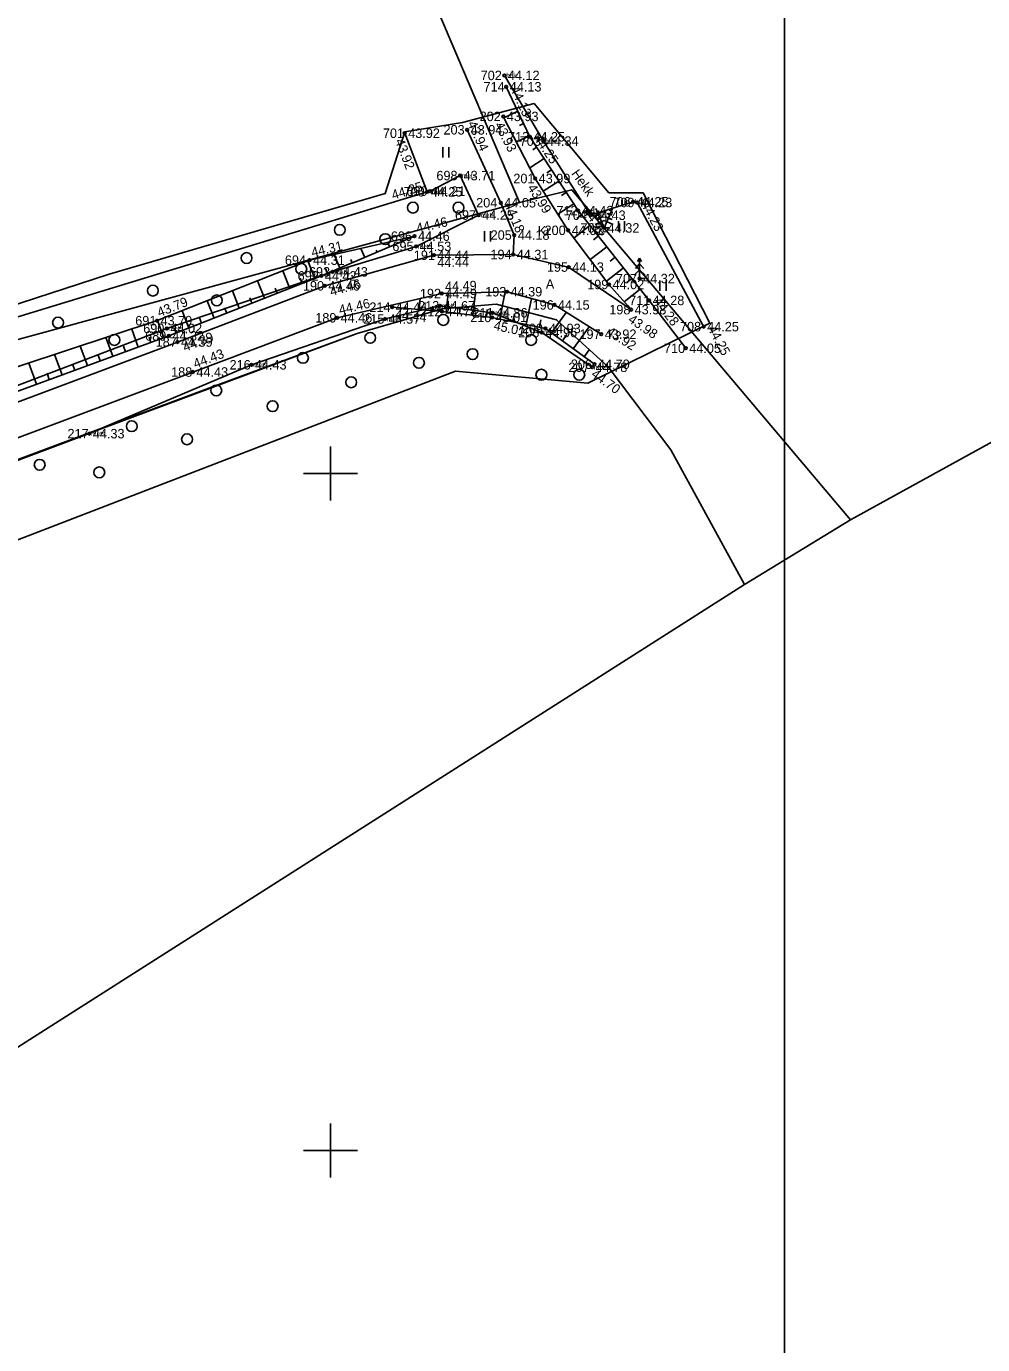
# Model space of a CAD drawing. Extents: x 505800 to 507326, y 6540058 to 6542128.
# Drawn here: x 506527.5 to 506598.2, y 6540335.7 to 6540433 of the extents above; entities that cross this region are included whole.
import ezdxf

# ---------------------------------------------------------------- set-up
doc = ezdxf.new("R2010")
doc.units = 0
for name, color, linetype in [('AED', 7, 'Continuous'), ('HALJASTUS', 7, 'Continuous'), ('KORGUS-EH2000', 7, 'Continuous'), ('MAAMUDEL', 7, 'Continuous'), ('MOOTKORG-EH2000', 7, 'Continuous'), ('MOOTMPUNKT', 7, 'Continuous'), ('MOOTNR', 7, 'Continuous'), ('MOOTPIIR', 7, 'Continuous'), ('PIIR', 7, 'Continuous'), ('PUU', 7, 'Continuous'), ('RELJEEF', 7, 'Continuous'), ('TEE', 7, 'Continuous'), ('VORK', 7, 'Continuous'), ('VORMISTUS', 7, 'Continuous')]:
    doc.layers.add(name, color=color, linetype=linetype)

msp = doc.modelspace()

# ---------------------------------------------------------------- linework, layer by layer
at = {"layer": 'AED'}
msp.add_line((506572.65, 6540420.013), (506577.572, 6540410.845), dxfattribs=at)
msp.add_lwpolyline([(506555.478, 6540425.13), (506557.144, 6540420.803), (506466.236, 6540393.054), (506460.432, 6540391.544), (506453.59, 6540403.335)], dxfattribs=at)
at = {"layer": 'HALJASTUS'}
for p, q in [((506558.288, 6540424.099), (506558.288, 6540423.338)), ((506558.743, 6540424.099), (506558.743, 6540423.338)), ((506561.37, 6540417.89), (506561.37, 6540417.129)), ((506561.825, 6540417.89), (506561.825, 6540417.129)), ((506571.271, 6540418.646), (506571.271, 6540417.884)), ((506571.726, 6540418.646), (506571.726, 6540417.884)), ((506574.337, 6540414.25), (506574.337, 6540413.489)), ((506574.792, 6540414.25), (506574.792, 6540413.489))]:
    msp.add_line(p, q, dxfattribs=at)
for points in [[(506572.366, 6540420.068), (506569.205, 6540419.074), (506565.725, 6540424.549), (506562.844, 6540429.401)], [(506557.354, 6540420.848), (506559.573, 6540422.003), (506560.946, 6540419.087), (506556.322, 6540416.775), (506550.153, 6540414.892), (506537.908, 6540410.713), (506520.721, 6540404.149), (506508.163, 6540400.843), (506496.611, 6540397.759), (506493.383, 6540398.082), (506483.471, 6540394.371), (506478, 6540394.292), (506477.343, 6540396.444)], [(506413.936, 6540356.957), (506411.035, 6540361.537), (506411.476, 6540364.066), (506416.66, 6540366.321), (506428.112, 6540371.138), (506442.602, 6540377.508), (506445.225, 6540379.984), (506450.028, 6540381.664), (506456.825, 6540384.191), (506464.626, 6540386.148), (506480.51, 6540389.107), (506500.858, 6540392.966), (506504.844, 6540391.729), (506512.52, 6540393.396), (506515.37, 6540396.647), (506532.173, 6540402.941), (506544.149, 6540408.028), (506554.027, 6540411.411), (506558.081, 6540412.384), (506561.957, 6540411.866), (506565.619, 6540410.412), (506569.33, 6540407.843)]]:
    msp.add_lwpolyline(points, dxfattribs=at)
for centre in [(506556.087, 6540419.636), (506559.45, 6540419.636), (506550.682, 6540417.993), (506554.045, 6540417.312), (506543.796, 6540415.91), (506547.84, 6540415.109), (506536.87, 6540413.506), (506541.594, 6540412.785), (506529.863, 6540411.143), (506558.334, 6540411.341), (506534.027, 6540409.861), (506552.929, 6540410.019), (506564.82, 6540409.859), (506560.496, 6540408.817), (506547.964, 6540408.537), (506556.532, 6540408.176), (506551.527, 6540406.734), (506565.58, 6540407.295), (506568.383, 6540407.295), (506541.558, 6540406.133), (506545.722, 6540404.971), (506535.312, 6540403.489), (506539.396, 6540402.528), (506528.506, 6540400.645), (506532.91, 6540400.084)]:
    msp.add_circle(centre, 0.4, dxfattribs=at)
at = {"layer": 'KORGUS-EH2000'}
for centre in [(506562.844, 6540429.401), (506562.984, 6540428.562), (506562.766, 6540426.375), (506555.478, 6540425.13), (506560.096, 6540425.387), (506564.728, 6540424.868), (506565.725, 6540424.549), (506559.573, 6540422.003), (506565.119, 6540421.785), (506557.144, 6540420.803), (506557.354, 6540420.848), (506562.58, 6540419.998), (506572.366, 6540420.068), (506572.65, 6540420.013), (506560.946, 6540419.087), (506568.304, 6540419.414), (506569.205, 6540419.074), (506563.58, 6540417.61), (506567.566, 6540417.958), (506570.222, 6540418.135), (506556.207, 6540417.529), (506556.322, 6540416.775), (506548.446, 6540415.756), (506557.625, 6540416.116), (506563.498, 6540416.176), (506550.153, 6540414.892), (506567.596, 6540415.247), (506549.32, 6540414.59), (506549.569, 6540413.859), (506570.577, 6540413.961), (506572.841, 6540414.395), (506558.214, 6540413.286), (506563.041, 6540413.426), (506573.539, 6540412.782), (506554.549, 6540412.283), (506558.081, 6540412.384), (506558.234, 6540411.96), (506561.957, 6540411.866), (506566.541, 6540412.447), (506572.209, 6540412.1), (506537.177, 6540411.287), (506550.483, 6540411.5), (506554.027, 6540411.411), (506561.931, 6540411.527), (506577.572, 6540410.845), (506537.908, 6540410.713), (506538.05, 6540410.165), (506565.619, 6540410.412), (506565.885, 6540410.713), (506570.003, 6540410.285), (506538.684, 6540409.711), (506576.247, 6540409.247), (506544.149, 6540408.028), (506569.506, 6540408.068), (506539.83, 6540407.495), (506569.33, 6540407.843), (506532.173, 6540402.941)]:
    msp.add_circle(centre, 0.1, dxfattribs=at)
at = {"layer": 'MOOTMPUNKT'}
for centre in [(506562.844, 6540429.401), (506562.984, 6540428.562), (506562.766, 6540426.375), (506555.478, 6540425.13), (506560.096, 6540425.387), (506564.728, 6540424.868), (506565.725, 6540424.549), (506559.573, 6540422.003), (506565.119, 6540421.785), (506557.144, 6540420.803), (506557.354, 6540420.848), (506562.58, 6540419.998), (506572.366, 6540420.068), (506572.65, 6540420.013), (506560.946, 6540419.087), (506568.304, 6540419.414), (506569.205, 6540419.074), (506563.58, 6540417.61), (506567.566, 6540417.958), (506570.222, 6540418.135), (506556.207, 6540417.529), (506556.322, 6540416.775), (506548.446, 6540415.756), (506557.625, 6540416.116), (506563.498, 6540416.176), (506550.153, 6540414.892), (506567.596, 6540415.247), (506549.32, 6540414.59), (506549.569, 6540413.859), (506570.577, 6540413.961), (506572.841, 6540414.395), (506558.214, 6540413.286), (506563.041, 6540413.426), (506573.539, 6540412.782), (506554.549, 6540412.283), (506558.081, 6540412.384), (506558.234, 6540411.96), (506561.957, 6540411.866), (506566.541, 6540412.447), (506572.209, 6540412.1), (506537.177, 6540411.287), (506550.483, 6540411.5), (506554.027, 6540411.411), (506561.931, 6540411.527), (506577.572, 6540410.845), (506537.908, 6540410.713), (506538.05, 6540410.165), (506565.619, 6540410.412), (506565.885, 6540410.713), (506570.003, 6540410.285), (506538.684, 6540409.711), (506576.247, 6540409.247), (506544.149, 6540408.028), (506569.506, 6540408.068), (506539.83, 6540407.495), (506569.33, 6540407.843), (506532.173, 6540402.941)]:
    msp.add_circle(centre, 0.1, dxfattribs=at)
at = {"layer": 'MOOTPIIR'}
msp.add_lwpolyline([(506461.402, 6540393.473), (506495.448, 6540402.285), (506533.638, 6540414.716), (506554.037, 6540420.685), (506555.478, 6540425.23), (506559.762, 6540425.933), (506565.047, 6540427.335), (506570.572, 6540420.725), (506573.094, 6540420.725), (506578.034, 6540411.094), (506569.01, 6540406.663), (506559.222, 6540407.565), (506515.922, 6540390.879), (506495.183, 6540386.603), (506455.807, 6540378.751)], dxfattribs=at)
at = {"layer": 'PIIR'}
for points in [[(506527.76, 6540505.12), (506551.71, 6540517.46), (506674.03, 6540580.08), (506675.04, 6540577.53), (506681.73, 6540560.57), (506720.48, 6540463.41), (506634.74, 6540422.06), (506588.42, 6540396.58), (506567.83, 6540420.95), (506563.96, 6540420.02)], [(506527.76, 6540505.12), (506563.96, 6540420.02), (506458.7, 6540391.28), (506429.21, 6540436.36), (506427.6, 6540438.79), (506466.35, 6540463.04), (506513.09, 6540491.84), (506518.32, 6540495.02), (506520.1, 6540496.45)], [(506462.8, 6540384.69), (506497.85, 6540391.32), (506509.27, 6540394.46), (506551.97, 6540410.35), (506558.26, 6540412.17), (506562.23, 6540412.5), (506566.7, 6540411.34), (506570.51, 6540407.87), (506575.14, 6540401.74), (506580.6, 6540391.81), (506495.14, 6540337.45)]]:
    msp.add_lwpolyline(points, close=True, dxfattribs=at)
msp.add_lwpolyline([(506458.7, 6540391.28), (506563.96, 6540420.02), (506567.83, 6540420.95), (506588.42, 6540396.58), (506580.6, 6540391.81), (506575.14, 6540401.74), (506570.51, 6540407.87), (506566.7, 6540411.34), (506562.23, 6540412.5), (506558.26, 6540412.17), (506551.97, 6540410.35), (506541.41, 6540406.45), (506509.27, 6540394.46), (506497.85, 6540391.32), (506462.8, 6540384.69)], dxfattribs=at)
at = {"layer": 'PUU'}
for p, q in [((506570.222, 6540418.679), (506569.565, 6540418.397)), ((506570.222, 6540418.135), (506569.601, 6540419.582)), ((506570.182, 6540418.988), (506569.631, 6540418.752)), ((506569.926, 6540419.205), (506569.65, 6540419.086)), ((506570.222, 6540418.135), (506570.843, 6540419.582)), ((506570.222, 6540418.679), (506570.879, 6540418.397)), ((506570.262, 6540418.988), (506570.813, 6540418.752)), ((506570.518, 6540419.205), (506570.793, 6540419.086)), ((506570.582, 6540418.135), (506570.222, 6540418.135)), ((506572.841, 6540415.895), (506572.691, 6540415.645)), ((506572.991, 6540415.645), (506572.841, 6540415.895)), ((506572.841, 6540415.895), (506572.841, 6540414.395)), ((506572.841, 6540415.045), (506572.441, 6540414.645)), ((506572.841, 6540415.495), (506572.541, 6540415.145)), ((506573.141, 6540415.145), (506572.841, 6540415.495)), ((506573.241, 6540414.645), (506572.841, 6540415.045)), ((506573.201, 6540414.395), (506572.841, 6540414.395))]:
    msp.add_line(p, q, dxfattribs=at)
at = {"layer": 'RELJEEF'}
for p, q in [((506563.838, 6540426.753), (506562.818, 6540426.272)), ((506564.265, 6540425.849), (506563.968, 6540425.709)), ((506564.692, 6540424.945), (506563.731, 6540424.491)), ((506565.23, 6540424.103), (506564.938, 6540423.912)), ((506565.778, 6540423.267), (506564.716, 6540422.57)), ((506566.327, 6540422.43), (506565.984, 6540422.206)), ((506566.875, 6540421.594), (506565.724, 6540420.839)), ((506567.423, 6540420.758), (506567.075, 6540420.53)), ((506567.971, 6540419.921), (506566.801, 6540419.154)), ((506568.548, 6540419.105), (506568.206, 6540418.835)), ((506569.167, 6540418.32), (506567.992, 6540417.393)), ((506554.368, 6540416.744), (506554.226, 6540417.076)), ((506555.287, 6540417.136), (506555.266, 6540417.186)), ((506556.207, 6540417.529), (506556.207, 6540417.529)), ((506570.407, 6540416.751), (506569.196, 6540415.795)), ((506569.787, 6540417.536), (506569.429, 6540417.253)), ((506550.689, 6540415.174), (506550.263, 6540416.171)), ((506551.608, 6540415.566), (506551.502, 6540415.816)), ((506552.528, 6540415.959), (506552.245, 6540416.623)), ((506553.448, 6540416.351), (506553.384, 6540416.501)), ((506571.026, 6540415.966), (506570.658, 6540415.675)), ((506546.982, 6540413.672), (506546.471, 6540414.973)), ((506548.843, 6540414.403), (506548.33, 6540415.71)), ((506549.769, 6540414.781), (506549.62, 6540415.13)), ((506571.646, 6540415.181), (506570.399, 6540414.197)), ((506545.12, 6540412.941), (506544.612, 6540414.235)), ((506547.913, 6540414.037), (506547.759, 6540414.429)), ((506572.265, 6540414.396), (506571.898, 6540414.106)), ((506543.258, 6540412.21), (506542.753, 6540413.498)), ((506544.189, 6540412.575), (506544.037, 6540412.963)), ((506546.051, 6540413.306), (506545.898, 6540413.696)), ((506556.542, 6540412.109), (506556.612, 6540412.916)), ((506558.533, 6540411.925), (506558.694, 6540413.3)), ((506560.519, 6540411.692), (506560.715, 6540413.359)), ((506562.498, 6540411.41), (506562.912, 6540413.423)), ((506564.457, 6540411.007), (506564.851, 6540412.92)), ((506572.885, 6540413.611), (506571.702, 6540412.677)), ((506539.535, 6540410.748), (506539.034, 6540412.023)), ((506541.397, 6540411.479), (506540.894, 6540412.761)), ((506542.328, 6540411.845), (506542.176, 6540412.23)), ((506554.549, 6540412.283), (506554.563, 6540412.443)), ((506555.545, 6540412.196), (506555.558, 6540412.341)), ((506557.538, 6540412.021), (506557.567, 6540412.361)), ((506559.526, 6540411.809), (506559.58, 6540412.265)), ((506561.513, 6540411.576), (506561.576, 6540412.12)), ((506566.323, 6540410.393), (506567.421, 6540411.897)), ((506537.67, 6540410.026), (506537.205, 6540411.298)), ((506540.466, 6540411.114), (506540.315, 6540411.497)), ((506563.477, 6540411.209), (506563.6, 6540411.803)), ((506565.436, 6540410.805), (506565.55, 6540411.359)), ((506533.913, 6540408.653), (506533.405, 6540410.042)), ((506535.792, 6540409.339), (506535.306, 6540410.669)), ((506536.731, 6540409.683), (506536.588, 6540410.073)), ((506538.604, 6540410.383), (506538.454, 6540410.764)), ((506567.13, 6540409.803), (506567.472, 6540410.272)), ((506567.938, 6540409.213), (506569.122, 6540410.835)), ((506532.035, 6540407.966), (506531.505, 6540409.415)), ((506534.853, 6540408.996), (506534.703, 6540409.404)), ((506568.745, 6540408.624), (506569.113, 6540409.128)), ((506528.278, 6540406.592), (506527.705, 6540408.16)), ((506530.157, 6540407.279), (506529.605, 6540408.787)), ((506531.096, 6540407.622), (506530.934, 6540408.066)), ((506532.974, 6540408.309), (506532.818, 6540408.735)), ((506529.217, 6540406.936), (506529.049, 6540407.397))]:
    msp.add_line(p, q, dxfattribs=at)
for points in [[(506562.984, 6540428.562), (506564.728, 6540424.868), (506568.304, 6540419.414), (506573.539, 6540412.782), (506576.247, 6540409.247)], [(506556.207, 6540417.529), (506548.446, 6540415.756), (506537.177, 6540411.287), (506507.092, 6540401.356), (506493.818, 6540397.458), (506479.74, 6540393.488), (506463.711, 6540390.977), (506454.162, 6540389.588), (506445.961, 6540387.82), (506436.644, 6540384.929), (506428.217, 6540381.232), (506425.206, 6540377.812), (506418.006, 6540373.612), (506396.112, 6540362.165), (506387.822, 6540357.514)], [(506556.207, 6540417.529), (506549.32, 6540414.59), (506538.05, 6540410.165), (506520.494, 6540403.746), (506508.114, 6540399.97), (506494.198, 6540395.848), (506479.734, 6540392.802), (506464.199, 6540389.877), (506454.62, 6540387.729), (506446.277, 6540385.845), (506437.645, 6540382.533), (506432.878, 6540380.89), (506430.375, 6540378.218), (506418.514, 6540372.235), (506396.686, 6540360.667), (506388.239, 6540356.069)], [(506554.549, 6540412.283), (506558.234, 6540411.96), (506561.931, 6540411.527), (506565.885, 6540410.713), (506569.506, 6540408.068)]]:
    msp.add_lwpolyline(points, dxfattribs=at)
at = {"layer": 'TEE'}
for points in [[(506562.766, 6540426.375), (506565.119, 6540421.785), (506567.566, 6540417.958), (506570.577, 6540413.961), (506572.209, 6540412.1)], [(506563.498, 6540416.176), (506563.58, 6540417.61), (506562.58, 6540419.998), (506560.096, 6540425.387)], [(506572.209, 6540412.1), (506567.596, 6540415.247), (506563.498, 6540416.176), (506557.625, 6540416.116), (506549.569, 6540413.859), (506538.684, 6540409.711), (506523.106, 6540403.859), (506508.948, 6540399.065), (506495.295, 6540395.538), (506478.706, 6540392.058), (506464.091, 6540389.4)], [(506570.003, 6540410.285), (506566.541, 6540412.447), (506563.041, 6540413.426), (506558.214, 6540413.286), (506550.483, 6540411.5), (506539.83, 6540407.495), (506524.028, 6540401.568), (506509.855, 6540396.74), (506495.782, 6540393.218), (506479.167, 6540389.797), (506464.651, 6540387.028)]]:
    msp.add_lwpolyline(points, dxfattribs=at)
at = {"layer": 'VORK'}
for p, q in [((506550, 6540402), (506550, 6540398)), ((506548, 6540400), (506552, 6540400)), ((506550, 6540352), (506550, 6540348)), ((506548, 6540350), (506552, 6540350))]:
    msp.add_line(p, q, dxfattribs=at)
at = {"layer": 'VORMISTUS'}
msp.add_lwpolyline([(506001.54, 6540083.849), (506001.54, 6540499.349), (506583.541, 6540499.349), (506583.541, 6540083.849)], close=True, dxfattribs=at)

# ---------------------------------------------------------------- texts
at = {"layer": 'HALJASTUS'}
msp.add_text('Hekk', height=0.7, rotation=305.23629, dxfattribs=at).set_placement((506567.758, 6540422.142))
at = {"layer": 'KORGUS-EH2000'}
for s, rotation, p in [(' 44.13', 295.28406, (506563.142, 6540428.637)), (' 43.94', 294.75093, (506559.99, 6540426.088)), (' 43.93', 297.14829, (506561.987, 6540425.975)), (' 43.92', 291.06235, (506554.661, 6540424.816)), (' 44.25', 303.24783, (506564.875, 6540424.964)), (' 44.25', 16.97445, (506554.382, 6540420.142)), (' 43.99', 302.59561, (506564.382, 6540421.314)), (' 44.18', 292.71892, (506562.726, 6540420.103)), (' 44.23', 298.22952, (506572.804, 6540420.096)), (' 44.46', 12.86688, (506556.168, 6540417.699)), (' 44.43', 308.28722, (506568.441, 6540419.522)), (' 44.31', 12.86688, (506548.407, 6540415.926)), (' 44.44', 0.5902, (506557.634, 6540415.241)), (' 44.46', 15.6457, (506549.805, 6540413.017)), (' 44.49', 1.66477, (506558.209, 6540413.461)), (' 43.79', 21.63254, (506537.113, 6540411.45)), (' 44.46', 13.00907, (506550.443, 6540411.67)), (' 44.28', 307.45195, (506573.678, 6540412.889)), (' 44.44', 354.98859, (506554.473, 6540411.412)), (' 45.01', 348.36326, (506561.755, 6540410.67)), (' 43.98', 325.69012, (506571.715, 6540411.377)), (' 44.39', 20.86461, (506538.996, 6540408.893)), (' 43.92', 328.01694, (506570.095, 6540410.434)), (' 44.25', 298.22952, (506577.726, 6540410.928)), (' 44.43', 20.60189, (506539.768, 6540407.659)), (' 44.70', 323.85547, (506568.99, 6540407.362))]:
    msp.add_text(s, height=0.7, rotation=rotation, dxfattribs=at).set_placement(p)
for s, p in [(' 44.43', (506544.149, 6540407.678)), (' 44.33', (506532.173, 6540402.591))]:
    msp.add_text(s, height=0.7, dxfattribs=at).set_placement(p)
at = {"layer": 'MAAMUDEL'}
for s, p in [(' hek', (506562.844, 6540429.226)), (' hek', (506565.725, 6540424.374)), (' mets', (506559.573, 6540421.828)), (' mets', (506557.354, 6540420.673)), (' hek', (506572.366, 6540419.893)), (' mets', (506560.946, 6540418.912)), (' hek', (506569.205, 6540418.899)), (' mets', (506556.322, 6540416.6)), (' mets', (506550.153, 6540414.717)), (' mets', (506558.081, 6540412.209)), (' mets', (506561.957, 6540411.691)), (' mets', (506554.027, 6540411.236)), (' mets', (506537.908, 6540410.538)), (' mets', (506565.619, 6540410.237)), (' mets', (506544.149, 6540407.853)), (' mets', (506569.33, 6540407.668)), (' mets', (506532.173, 6540402.766))]:
    msp.add_text(s, height=0.35, dxfattribs=at).set_placement(p)
at = {"layer": 'MOOTKORG-EH2000'}
for s, p in [(' 44.12', (506562.844, 6540429.052)), (' 44.13', (506562.984, 6540428.212)), (' 43.93', (506562.766, 6540426.025)), (' 43.94', (506560.096, 6540425.036)), (' 43.92', (506555.478, 6540424.78)), (' 44.25', (506564.728, 6540424.518)), (' 44.34', (506565.725, 6540424.199)), (' 43.71', (506559.573, 6540421.652)), (' 43.99', (506565.119, 6540421.435)), (' 44.25', (506557.144, 6540420.453)), (' 44.21', (506557.354, 6540420.498)), (' 44.05', (506562.58, 6540419.648)), (' 44.43', (506568.304, 6540419.064)), (' 44.25', (506572.366, 6540419.718)), (' 44.23', (506572.65, 6540419.663)), (' 44.25', (506560.946, 6540418.737)), (' 44.43', (506569.205, 6540418.724)), (' 44.46', (506556.207, 6540417.179)), (' 44.18', (506563.58, 6540417.26)), (' 44.03', (506567.566, 6540417.608)), (' 44.32', (506570.222, 6540417.785)), (' 44.53', (506556.322, 6540416.425)), (' 44.31', (506548.446, 6540415.406)), (' 44.44', (506557.625, 6540415.766)), (' 44.31', (506563.498, 6540415.826)), (' 44.42', (506549.32, 6540414.24)), (' 44.43', (506550.153, 6540414.542)), (' 44.13', (506567.596, 6540414.897)), (' 44.46', (506549.569, 6540413.509)), (' 44.02', (506570.577, 6540413.611)), (' 44.32', (506572.841, 6540414.045)), (' 44.49', (506558.214, 6540412.936)), (' 44.39', (506563.041, 6540413.076)), (' 44.28', (506573.539, 6540412.432)), (' 44.44', (506554.549, 6540411.933)), (' 44.67', (506558.081, 6540412.034)), (' 44.78', (506558.234, 6540411.61)), (' 45.01', (506561.931, 6540411.177)), (' 44.86', (506561.957, 6540411.516)), (' 44.15', (506566.541, 6540412.097)), (' 43.98', (506572.209, 6540411.75)), (' 43.79', (506537.177, 6540410.937)), (' 44.02', (506537.908, 6540410.363)), (' 44.46', (506550.483, 6540411.15)), (' 44.57', (506554.027, 6540411.061)), (' 44.93', (506565.885, 6540410.363)), (' 44.25', (506577.572, 6540410.495)), (' 44.32', (506538.05, 6540409.815)), (' 44.39', (506538.684, 6540409.36)), (' 44.96', (506565.619, 6540410.062)), (' 43.92', (506570.003, 6540409.935)), (' 44.05', (506576.247, 6540408.897)), (' 44.43', (506544.149, 6540407.678)), (' 44.78', (506569.33, 6540407.493)), (' 44.70', (506569.506, 6540407.718)), (' 44.43', (506539.83, 6540407.145)), (' 44.33', (506532.173, 6540402.591))]:
    msp.add_text(s, height=0.7, dxfattribs=at).set_placement(p)
at = {"layer": 'MOOTNR'}
for s, p in [('702 ', (506561.094, 6540429.052)), ('714 ', (506561.304, 6540428.212)), ('202 ', (506561.016, 6540426.025)), ('203 ', (506558.346, 6540425.036)), ('701 ', (506553.868, 6540424.78)), ('713 ', (506563.118, 6540424.518)), ('703 ', (506563.975, 6540424.199)), ('698 ', (506557.823, 6540421.652)), ('201 ', (506563.509, 6540421.435)), ('700 ', (506555.394, 6540420.453)), ('699 ', (506555.604, 6540420.498)), ('204 ', (506560.76, 6540419.648)), ('712 ', (506566.694, 6540419.064)), ('706 ', (506570.616, 6540419.718)), ('709 ', (506570.9, 6540419.663)), ('697 ', (506559.196, 6540418.737)), ('704 ', (506567.385, 6540418.724)), ('696 ', (506554.457, 6540417.179)), ('205 ', (506561.83, 6540417.26)), ('200 ', (506565.816, 6540417.608)), ('705 ', (506568.472, 6540417.785)), ('695 ', (506554.572, 6540416.425)), ('694 ', (506546.626, 6540415.406)), ('191 ', (506556.155, 6540415.766)), ('194 ', (506561.818, 6540415.826)), ('692 ', (506547.57, 6540414.24)), ('693 ', (506548.403, 6540414.542)), ('195 ', (506565.986, 6540414.897)), ('190 ', (506547.959, 6540413.509)), ('199 ', (506568.967, 6540413.611)), ('707 ', (506571.091, 6540414.045)), ('192 ', (506556.604, 6540412.936)), ('193 ', (506561.431, 6540413.076)), ('711 ', (506572.069, 6540412.432)), ('214 ', (506552.869, 6540411.933)), ('213 ', (506556.471, 6540412.034)), ('212 ', (506556.624, 6540411.61)), ('210 ', (506560.321, 6540411.177)), ('211 ', (506560.487, 6540411.516)), ('196 ', (506564.931, 6540412.097)), ('198 ', (506570.599, 6540411.75)), ('691 ', (506535.568, 6540410.937)), ('690 ', (506536.158, 6540410.363)), ('189 ', (506548.873, 6540411.15)), ('215 ', (506552.417, 6540411.061)), ('209 ', (506564.135, 6540410.363)), ('708 ', (506575.822, 6540410.495)), ('689 ', (506536.3, 6540409.815)), ('187 ', (506537.074, 6540409.36)), ('208 ', (506563.869, 6540410.062)), ('197 ', (506568.393, 6540409.935)), ('710 ', (506574.637, 6540408.897)), ('216 ', (506542.539, 6540407.678)), ('207 ', (506567.58, 6540407.493)), ('206 ', (506567.756, 6540407.718)), ('188 ', (506538.22, 6540407.145)), ('217 ', (506530.563, 6540402.591))]:
    msp.add_text(s, height=0.7, dxfattribs=at).set_placement(p)
at = {"layer": 'TEE'}
for s, p in [('Kr', (506565.308, 6540417.567)), ('A', (506565.908, 6540413.641))]:
    msp.add_text(s, height=0.7, dxfattribs=at).set_placement(p)

doc.saveas('drawing.dxf')
